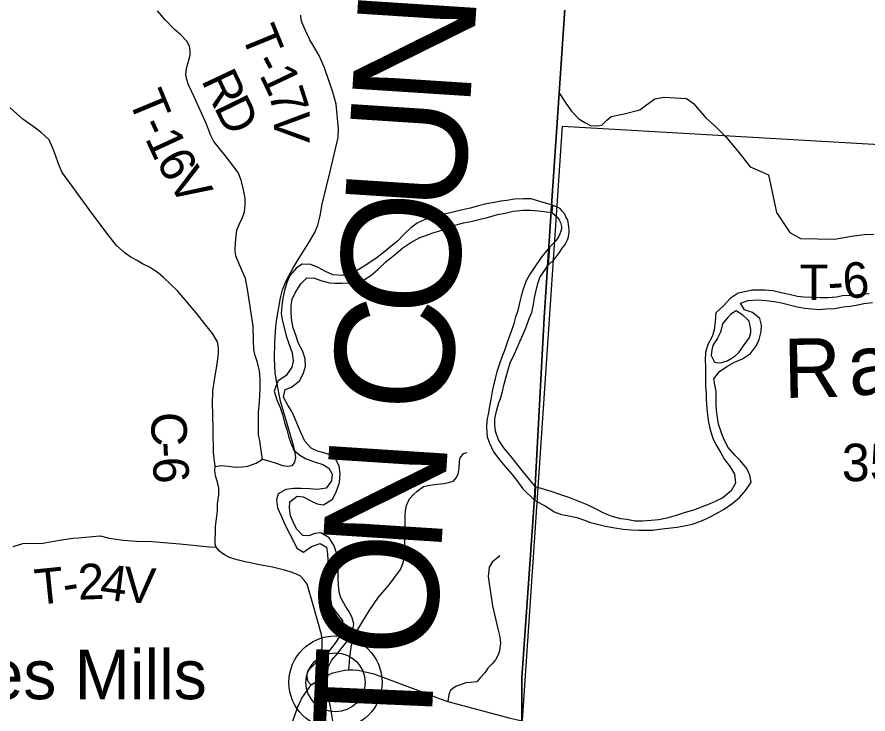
# Model space of a CAD drawing. Extents: x 0 to 34, y 0 to 22.
# Drawn here: x 3.447 to 4.807, y 18.997 to 20.111 of the extents above; entities that cross this region are included whole.
import ezdxf

# ---------------------------------------------------------------- set-up
doc = ezdxf.new("R2010")
doc.units = 0
for name, color, linetype in [('GM_X_Corporation', 7, 'Continuous'), ('GM_X_County_Road', 7, 'Continuous'), ('GM_X_County_Road_Text', 7, 'Continuous'), ('GM_X_County_Text', 7, 'Continuous'), ('GM_X_Major_River', 7, 'Continuous'), ('GM_X_Major_River_Text', 7, 'Continuous'), ('GM_X_Section_Text', 7, 'Continuous'), ('GM_X_Township_Road', 7, 'Continuous'), ('GM_X_Township_Road_Text', 7, 'Continuous'), ('GM_X_Township_Text', 7, 'Continuous'), ('GM_X_Unincorporated', 7, 'Continuous'), ('GM_X_Unincorporated_Location', 7, 'Continuous'), ('GM_X_Unincorporated_Text', 7, 'Continuous')]:
    doc.layers.add(name, color=color, linetype=linetype)

msp = doc.modelspace()

# ---------------------------------------------------------------- linework, layer by layer
at = {"layer": 'GM_X_Corporation'}
msp.add_lwpolyline([(4.1215, 17.0136), (4.1603, 17.6679), (4.1853, 18.0392), (4.1964, 18.2095), (4.2079, 18.3668), (4.2088, 18.3789), (4.2282, 18.6426), (4.2537, 18.9868), (4.2536, 19.0552), (4.2737, 19.3421), (4.2893, 19.6309), (4.3029, 19.8336), (4.3134, 19.9898), (4.3401, 20.3869), (4.364, 20.7926), (4.3772, 20.9), (2.1, 20.9), (2.1, 14.9497)], dxfattribs=at)
msp.add_lwpolyline([(5.342, 19.878), (5.2756, 18.8667), (4.2512, 18.9319), (4.3184, 19.9368)], close=True, dxfattribs=at)
at = {"layer": 'GM_X_County_Road'}
for points in [[(3.9168, 19.0437), (3.9128, 19.0479), (3.911, 19.0525), (3.9102, 19.0601), (3.9116, 19.0653), (3.9154, 19.0699), (3.9194, 19.0745), (3.9274, 19.0829), (3.9316, 19.0895), (3.934, 19.0973), (3.9346, 19.1073), (3.9342, 19.1163), (3.9332, 19.1241), (3.9204, 19.1697), (3.9104, 19.2048), (3.9056, 19.211), (3.899, 19.2182), (3.8908, 19.2218), (3.883, 19.2248), (3.8742, 19.227), (3.8654, 19.2294), (3.855, 19.2318), (3.8433, 19.2342), (3.8311, 19.2362), (3.8197, 19.2388), (3.8113, 19.2406), (3.8007, 19.2432), (3.7925, 19.2452), (3.7853, 19.2482), (3.7791, 19.251), (3.7737, 19.2548), (3.7695, 19.2582), (3.7647, 19.2638), (3.7633, 19.2686), (3.7633, 19.2778), (3.7639, 19.2848), (3.7641, 19.2968), (3.7655, 19.3094), (3.7669, 19.3218), (3.7673, 19.3335), (3.7693, 19.3479), (3.7693, 19.3585), (3.7669, 19.3681), (3.7637, 19.3779), (3.7629, 19.3865), (3.7635, 19.3931), (3.7607, 19.4154), (3.7602, 19.4506), (3.7594, 19.4782), (3.7589, 19.4922), (3.7596, 19.5133), (3.7622, 19.5317), (3.7647, 19.5471), (3.7671, 19.561), (3.7686, 19.5733), (3.7688, 19.583), (3.7671, 19.5922), (3.7592, 19.6054), (3.7485, 19.6189), (3.7332, 19.6388), (3.703, 19.674), (3.6806, 19.6953), (3.6721, 19.7027), (3.6665, 19.7065), (3.6581, 19.7115), (3.6472, 19.7167), (3.6384, 19.722), (3.6285, 19.7274), (3.6193, 19.734), (3.6058, 19.7462), (3.5902, 19.7661), (3.5619, 19.8036), (3.5318, 19.845), (3.5189, 19.8631), (3.5129, 19.8766), (3.5081, 19.8906), (3.5035, 19.9027), (3.4979, 19.9149), (3.4859, 19.9266), (3.4763, 19.934), (3.4561, 19.948), (3.4313, 19.9702)], [(3.9168, 19.0437), (3.9261, 19.0496), (3.9355, 19.0554), (3.9447, 19.06), (3.9516, 19.0629), (3.9608, 19.0652), (3.9701, 19.0674), (3.9771, 19.0681), (3.9835, 19.0677), (3.992, 19.0674), (4.001, 19.065), (4.0168, 19.0614), (4.0442, 19.0511), (4.0739, 19.0399), (4.1079, 19.0272), (4.1213, 19.0223), (4.1351, 19.017), (4.2352, 18.9904), (4.2539, 18.9862)], [(3.5195, 18.4353), (3.5205, 18.4371), (3.5398, 18.4705), (3.5489, 18.484), (3.5628, 18.5), (3.5942, 18.5239), (3.6761, 18.5868), (3.7791, 18.6664), (3.7951, 18.68), (3.809, 18.6975), (3.8193, 18.716), (3.8275, 18.7388), (3.8353, 18.7655), (3.8433, 18.8163), (3.8461, 18.8329), (3.8573, 18.885), (3.8738, 18.9436), (3.8854, 18.9794), (3.8952, 19.0076), (3.9018, 19.0226), (3.9168, 19.0437)]]:
    msp.add_lwpolyline(points, dxfattribs=at)
at = {"layer": 'GM_X_Major_River'}
for p, q in [((4.3024, 19.8106), (4.3016, 19.7988)), ((4.2978, 19.7433), (4.2959, 19.715)), ((4.2757, 19.3602), (4.2745, 19.3384))]:
    msp.add_line(p, q, dxfattribs=at)
for points in [[(4.3024, 19.8106), (4.2825, 19.8168), (4.2684, 19.8206), (4.2563, 19.821), (4.2419, 19.8203), (4.2297, 19.8184), (4.2202, 19.8169), (4.2092, 19.815), (4.1974, 19.8127), (4.1845, 19.8097), (4.1712, 19.8059), (4.1564, 19.8025), (4.1462, 19.8002), (4.1344, 19.7972), (4.1237, 19.7953), (4.1131, 19.793), (4.1002, 19.7885), (4.0861, 19.7817), (4.0763, 19.7745), (4.0668, 19.7654), (4.0546, 19.7529), (4.0447, 19.7453), (4.0318, 19.7347), (4.0223, 19.7271), (4.012, 19.7199), (4.0014, 19.7131), (3.9919, 19.7074), (3.9778, 19.7013), (3.9657, 19.6983), (3.9516, 19.6994), (3.9399, 19.7044), (3.9281, 19.7108), (3.9163, 19.7158), (3.9027, 19.7162), (3.8932, 19.7105), (3.8829, 19.6984), (3.878, 19.687), (3.8741, 19.6745), (3.8715, 19.6619), (3.8699, 19.6498), (3.8688, 19.6377), (3.8703, 19.6278), (3.8767, 19.602), (3.8816, 19.588), (3.8862, 19.5747), (3.8881, 19.5614), (3.8858, 19.5519), (3.8767, 19.5383), (3.8637, 19.5292), (3.8576, 19.5136), (3.8618, 19.4996), (3.8671, 19.487), (3.8709, 19.476), (3.8743, 19.4635), (3.8777, 19.4521), (3.8807, 19.4415), (3.8838, 19.432), (3.8891, 19.4191), (3.8989, 19.4111), (3.9088, 19.4054), (3.9221, 19.4005), (3.9357, 19.3959), (3.9452, 19.3902), (3.9502, 19.3807), (3.9494, 19.3701), (3.9406, 19.3584), (3.927, 19.3561), (3.9141, 19.3572), (3.9011, 19.3576), (3.889, 19.3576), (3.8761, 19.3561), (3.8643, 19.3493), (3.8616, 19.3398), (3.8631, 19.3269), (3.8688, 19.314), (3.876, 19.2981), (3.8825, 19.2848), (3.8889, 19.2723), (3.8938, 19.2624), (3.9045, 19.256), (3.9174, 19.265), (3.9311, 19.27), (3.9413, 19.2639), (3.9432, 19.2533), (3.9436, 19.243), (3.9435, 19.2297), (3.9431, 19.2187), (3.9428, 19.2085), (3.9431, 19.196), (3.9443, 19.1857), (3.9477, 19.1724), (3.9568, 19.1595), (3.967, 19.147), (3.967, 19.1337), (3.9632, 19.1235), (3.9567, 19.1125), (3.9476, 19.1011), (3.9388, 19.0886), (3.9331, 19.0776), (3.9297, 19.0632), (3.9282, 19.0522)], [(4.2959, 19.715), (4.3057, 19.7244), (4.3091, 19.7289), (4.3122, 19.7327), (4.3149, 19.7369), (4.3183, 19.7418), (4.3217, 19.7463), (4.3244, 19.7509), (4.3267, 19.7554), (4.3282, 19.7599), (4.329, 19.7637), (4.3294, 19.7679), (4.3294, 19.7717), (4.329, 19.7759), (4.3283, 19.7797), (4.3275, 19.7839), (4.3264, 19.7877), (4.3242, 19.7918), (4.3223, 19.7964), (4.3181, 19.8013), (4.3151, 19.8055), (4.3024, 19.8106)], [(3.9445, 19.0286), (3.943, 19.0419), (3.9422, 19.0537), (3.9426, 19.0632), (3.9445, 19.0734), (3.9491, 19.0829), (3.9593, 19.0943), (3.9666, 19.1038), (3.9776, 19.1174), (3.9829, 19.1284), (3.9848, 19.1413), (3.9822, 19.1508), (3.978, 19.1603), (3.9716, 19.1698), (3.9644, 19.1831), (3.9617, 19.1925), (3.9606, 19.2035), (3.9598, 19.2134), (3.9599, 19.2248), (3.9595, 19.2388), (3.9587, 19.2498), (3.9538, 19.2662), (3.9455, 19.2791), (3.9322, 19.2867), (3.9227, 19.2859), (3.9132, 19.2821), (3.9037, 19.2825), (3.8935, 19.2935), (3.8882, 19.3045), (3.884, 19.314), (3.8821, 19.3269), (3.8829, 19.3364), (3.8943, 19.3455), (3.9042, 19.3444), (3.9163, 19.3383), (3.9266, 19.3333), (3.9364, 19.3318), (3.9509, 19.3405), (3.957, 19.3519), (3.9619, 19.3671), (3.9634, 19.3815), (3.9616, 19.394), (3.954, 19.4084), (3.9392, 19.4145), (3.9267, 19.4176), (3.9168, 19.4225), (3.9065, 19.4335), (3.9009, 19.446), (3.8956, 19.4586), (3.8906, 19.4703), (3.8861, 19.481), (3.8796, 19.4908), (3.8724, 19.5037), (3.8755, 19.5159), (3.8854, 19.52), (3.8983, 19.5299), (3.904, 19.5409), (3.9078, 19.5526), (3.9071, 19.5648), (3.9033, 19.5769), (3.8968, 19.5898), (3.8923, 19.6031), (3.8878, 19.6145), (3.8859, 19.6255), (3.8847, 19.6388), (3.8851, 19.6498), (3.8867, 19.6604), (3.8912, 19.6703), (3.9004, 19.6851), (3.9099, 19.6945), (3.922, 19.6938), (3.9323, 19.6904), (3.9459, 19.6866), (3.9554, 19.6858), (3.9664, 19.6858), (3.9771, 19.6865), (3.9911, 19.6877), (4.0006, 19.6907), (4.012, 19.6983), (4.0234, 19.7081), (4.0363, 19.7199), (4.0493, 19.7309), (4.0633, 19.7426), (4.0762, 19.751), (4.0903, 19.7589), (4.1002, 19.7623), (4.1116, 19.7665), (4.1226, 19.7695), (4.1385, 19.776), (4.1484, 19.7794), (4.1606, 19.7824), (4.1723, 19.7847), (4.1872, 19.7881), (4.1989, 19.7911), (4.2149, 19.7956), (4.227, 19.7979), (4.2396, 19.8013), (4.2559, 19.8028), (4.2673, 19.8028), (4.2802, 19.8017), (4.3016, 19.7988)], [(4.3016, 19.7988), (4.3101, 19.7915), (4.3135, 19.7873), (4.3154, 19.7828), (4.3169, 19.7767), (4.3173, 19.7729), (4.3161, 19.7691), (4.3146, 19.7649), (4.313, 19.7611), (4.31, 19.757), (4.3069, 19.7528), (4.2978, 19.7433)], [(4.2978, 19.7433), (4.2847, 19.7269), (4.2744, 19.7121), (4.266, 19.6992), (4.2607, 19.6897), (4.2554, 19.6749), (4.2527, 19.6651), (4.2497, 19.6545), (4.247, 19.6423), (4.2432, 19.6302), (4.2401, 19.6192), (4.2367, 19.6086), (4.2329, 19.5987), (4.2291, 19.5881), (4.2257, 19.5786), (4.2215, 19.5676), (4.2177, 19.557), (4.2135, 19.5441), (4.2108, 19.5335), (4.2081, 19.5225), (4.2062, 19.5126), (4.2039, 19.5001), (4.202, 19.4895), (4.2001, 19.4792), (4.1978, 19.4663), (4.197, 19.4546), (4.1982, 19.4405), (4.202, 19.4303), (4.2084, 19.4162), (4.2183, 19.4033), (4.2262, 19.3934), (4.2384, 19.3802), (4.2459, 19.3703), (4.2554, 19.357), (4.2745, 19.3384)], [(4.2757, 19.3602), (4.2565, 19.3837), (4.2357, 19.4098), (4.2247, 19.423), (4.2164, 19.4356), (4.2115, 19.4496), (4.2103, 19.4591), (4.2104, 19.469), (4.213, 19.4815), (4.2161, 19.4929), (4.2203, 19.5035), (4.2229, 19.513), (4.2252, 19.5243), (4.2287, 19.5361), (4.2313, 19.5456), (4.2351, 19.5585), (4.2412, 19.5721), (4.2462, 19.5828), (4.2507, 19.5938), (4.2557, 19.6044), (4.2603, 19.6158), (4.2656, 19.6294), (4.2694, 19.6389), (4.2721, 19.6518), (4.274, 19.6624), (4.2759, 19.6719), (4.2793, 19.6856), (4.2824, 19.695), (4.2959, 19.715)], [(4.8092, 19.6692), (4.7955, 19.6681), (4.7815, 19.6665), (4.7664, 19.6657), (4.7566, 19.6634), (4.7429, 19.6626), (4.7304, 19.6626), (4.7172, 19.6629), (4.7043, 19.6636), (4.6941, 19.6648), (4.6812, 19.6677), (4.668, 19.6707), (4.6551, 19.6737), (4.6422, 19.6748), (4.6225, 19.6748), (4.6123, 19.6729), (4.5995, 19.6698), (4.5866, 19.6614), (4.576, 19.65), (4.5639, 19.6386), (4.5625, 19.6246), (4.561, 19.6109), (4.558, 19.6007), (4.5508, 19.5878), (4.5474, 19.5752), (4.5467, 19.5627), (4.5471, 19.5532), (4.5471, 19.5316), (4.5475, 19.5203), (4.5483, 19.5108), (4.5483, 19.5013), (4.5487, 19.4918), (4.5507, 19.4752), (4.5522, 19.4638), (4.5549, 19.4517), (4.5591, 19.438), (4.5636, 19.4282), (4.572, 19.4146), (4.5777, 19.4043), (4.5868, 19.3922), (4.5936, 19.3805), (4.5952, 19.3665), (4.5884, 19.354), (4.5752, 19.3429), (4.5627, 19.3372), (4.5529, 19.3326), (4.5283, 19.3231), (4.5147, 19.3192), (4.5003, 19.3147), (4.4852, 19.3104), (4.4727, 19.3078)], [(4.5408, 19.306), (4.5518, 19.311), (4.5639, 19.3171), (4.5771, 19.3247), (4.5896, 19.3335), (4.6017, 19.3434), (4.6119, 19.3552), (4.6202, 19.3681), (4.6183, 19.3791), (4.6133, 19.3897), (4.6034, 19.4021), (4.594, 19.4112), (4.5837, 19.4233), (4.5765, 19.4366), (4.5727, 19.4468), (4.5681, 19.4608), (4.5666, 19.4714), (4.565, 19.4832), (4.5643, 19.4926), (4.5642, 19.5127), (4.5623, 19.5233), (4.5604, 19.5332), (4.5694, 19.5446), (4.5815, 19.553), (4.5936, 19.5598), (4.6065, 19.5652), (4.619, 19.5735), (4.6288, 19.5865), (4.6333, 19.596), (4.6363, 19.6089), (4.637, 19.6191), (4.6344, 19.6297), (4.6226, 19.6391), (4.6097, 19.6433), (4.6033, 19.6539), (4.6154, 19.6581), (4.6298, 19.6593), (4.6445, 19.6582), (4.657, 19.6567), (4.6688, 19.6544), (4.6938, 19.6484), (4.7059, 19.6462), (4.718, 19.6451), (4.729, 19.644), (4.7396, 19.6448), (4.7543, 19.6456), (4.7676, 19.6483), (4.7785, 19.6494), (4.7884, 19.6506), (4.8005, 19.6533), (4.8141, 19.6552)], [(4.5961, 19.6417), (4.5878, 19.6364), (4.5829, 19.6311), (4.5791, 19.6269), (4.5746, 19.6208), (4.5727, 19.6136), (4.5712, 19.6079), (4.5667, 19.598), (4.5591, 19.5863), (4.5573, 19.5794), (4.5565, 19.5703), (4.5618, 19.5597)], [(4.5618, 19.5597), (4.5668, 19.5586), (4.5732, 19.5594), (4.5766, 19.5602), (4.5819, 19.5621), (4.5883, 19.5655), (4.5947, 19.5701), (4.6008, 19.575), (4.608, 19.586), (4.614, 19.5936), (4.6174, 19.5989), (4.6196, 19.6073), (4.62, 19.6118), (4.6173, 19.6251), (4.6151, 19.6274), (4.6067, 19.6349), (4.5961, 19.6417)], [(4.3193, 19.3466), (4.2987, 19.3534), (4.2757, 19.3602)], [(4.4727, 19.3078), (4.4602, 19.3066), (4.4466, 19.3054), (4.4344, 19.3057), (4.4216, 19.308), (4.4117, 19.3095), (4.3981, 19.3128), (4.3848, 19.3185), (4.3704, 19.326), (4.3568, 19.3324), (4.3435, 19.3377), (4.3303, 19.3426), (4.3193, 19.3466)], [(4.2745, 19.3384), (4.2921, 19.3296)], [(4.2921, 19.3296), (4.3053, 19.3205), (4.3171, 19.316), (4.3288, 19.3142), (4.3417, 19.3115), (4.3538, 19.3074), (4.3633, 19.3036), (4.3746, 19.301), (4.3875, 19.2977), (4.4023, 19.2947), (4.4159, 19.2928), (4.4288, 19.2917), (4.4405, 19.291), (4.4504, 19.291), (4.4625, 19.2914), (4.4738, 19.2926), (4.4878, 19.2941), (4.5015, 19.2957), (4.5166, 19.2988), (4.5264, 19.3007), (4.5408, 19.306)], [(3.9282, 19.0522), (3.927, 19.0393), (3.9266, 19.0264), (3.9266, 19.0165), (3.9277, 19.0051), (3.9315, 18.9896)], [(3.9516, 18.9865), (3.9494, 18.999), (3.9475, 19.0085), (3.9456, 19.0192), (3.9445, 19.0286)]]:
    msp.add_lwpolyline(points, dxfattribs=at)
at = {"layer": 'GM_X_Township_Road'}
for points in [[(3.7635, 19.3931), (3.7727, 19.3945), (3.7849, 19.3932), (3.7957, 19.3919), (3.8066, 19.3922), (3.8158, 19.3932), (3.829, 19.3981), (3.8388, 19.4049), (3.8372, 19.4149), (3.8346, 19.4343), (3.8328, 19.4432), (3.8324, 19.4703), (3.8324, 19.4791), (3.8341, 19.4963), (3.8351, 19.5175), (3.8354, 19.5325), (3.8344, 19.546), (3.8311, 19.5593), (3.827, 19.572), (3.8252, 19.58), (3.8247, 19.5943), (3.8239, 19.6172), (3.8152, 19.6763), (3.8119, 19.6935), (3.802, 19.7152), (3.7962, 19.7295), (3.7954, 19.7383), (3.7961, 19.7511), (3.7969, 19.7613), (3.7982, 19.7707), (3.8015, 19.7797), (3.8069, 19.7911), (3.8102, 19.8001), (3.8114, 19.8116), (3.8112, 19.822), (3.8084, 19.8351), (3.805, 19.8506), (3.8, 19.8631), (3.7791, 19.8899), (3.7614, 19.9124), (3.7558, 19.9231), (3.7497, 19.9404), (3.7298, 19.9838), (3.7206, 20.0031), (3.7179, 20.0114), (3.7165, 20.0195), (3.7175, 20.0294), (3.7203, 20.0387), (3.7232, 20.0503), (3.7235, 20.0577), (3.7221, 20.0649), (3.7178, 20.073), (3.7087, 20.083), (3.6984, 20.0914), (3.6834, 20.1072), (3.6712, 20.1215)], [(3.8388, 19.4049), (3.8507, 19.4013), (3.8624, 19.3978), (3.8711, 19.3945), (3.8795, 19.3934), (3.887, 19.3947), (3.8906, 19.3998), (3.8921, 19.4073), (3.8913, 19.4154), (3.889, 19.4246), (3.8862, 19.434), (3.8678, 19.4975), (3.8617, 19.5271), (3.8591, 19.5429), (3.8581, 19.5656), (3.8586, 19.5914), (3.8602, 19.6162), (3.8619, 19.6292), (3.8679, 19.6626), (3.8711, 19.6756), (3.8773, 19.6906), (3.8874, 19.7096), (3.8969, 19.7254), (3.902, 19.733), (3.9128, 19.7498), (3.9229, 19.7669), (3.9275, 19.7787), (3.9313, 19.7934), (3.9344, 19.8121), (3.9471, 19.8647), (3.9602, 19.919), (3.9605, 19.9327), (3.9568, 19.972), (3.9512, 19.9914), (3.9388, 20.0286), (3.9352, 20.0378), (3.9295, 20.0498), (3.9229, 20.0618), (3.9145, 20.0749), (3.9078, 20.0897), (3.9033, 20.0996), (3.901, 20.1065), (3.9002, 20.1144)], [(4.3136, 19.9893), (4.3242, 19.9737), (4.3331, 19.9611), (4.3446, 19.9488), (4.3541, 19.9427), (4.3633, 19.9379), (4.375, 19.9376), (4.3817, 19.9387), (4.3896, 19.9468), (4.3963, 19.9527), (4.4175, 19.9569), (4.4422, 19.9629), (4.4529, 19.9711), (4.4663, 19.9806), (4.4814, 19.9831), (4.499, 19.9823), (4.5169, 19.9812), (4.5281, 19.9731), (4.5476, 19.9505), (4.5635, 19.9365), (4.58, 19.92), (4.5987, 19.8969), (4.6185, 19.872), (4.6384, 19.8636), (4.6479, 19.8594), (4.6607, 19.7988), (4.6777, 19.7734)], [(4.6777, 19.7734), (4.6819, 19.767), (4.6992, 19.7575), (4.7533, 19.7565), (4.7807, 19.7611), (4.8017, 19.7637), (4.8162, 19.7645)], [(3.9771, 19.0681), (3.9775, 19.0734), (3.9786, 19.0883), (3.9815, 19.1078), (3.9867, 19.1241), (3.9978, 19.1431), (4.0097, 19.1623), (4.0244, 19.184), (4.0416, 19.2039), (4.0594, 19.2285), (4.0639, 19.2389), (4.0657, 19.2481), (4.0666, 19.272), (4.0662, 19.2842), (4.067, 19.3019), (4.0673, 19.3141), (4.0675, 19.3224), (4.0691, 19.3305), (4.074, 19.341), (4.0804, 19.3483), (4.0863, 19.3535), (4.0965, 19.3608), (4.1066, 19.3633), (4.1179, 19.3648), (4.1293, 19.3659), (4.1363, 19.3671), (4.1445, 19.3695), (4.1487, 19.3747), (4.1517, 19.3809), (4.1535, 19.3903), (4.1541, 19.4015), (4.1548, 19.4069), (4.1603, 19.4136), (4.1662, 19.4155)], [(3.4402, 19.2652), (3.456, 19.2697), (3.4663, 19.2702), (3.4851, 19.27), (3.5142, 19.2751), (3.5359, 19.2782), (3.5446, 19.2791), (3.5671, 19.2812), (3.5793, 19.2819), (3.5938, 19.2786), (3.6163, 19.2751), (3.6375, 19.2736), (3.6622, 19.273), (3.7066, 19.2694), (3.7541, 19.2644), (3.7647, 19.2638)], [(4.2182, 19.2501), (4.2064, 19.24), (4.2014, 19.2322), (4.1999, 19.2173), (4.2009, 19.2094), (4.2066, 19.1703), (4.2153, 19.1333), (4.2186, 19.1206), (4.2194, 19.1102), (4.2185, 19.1036), (4.2177, 19.0976), (4.2151, 19.0906), (4.2117, 19.0839), (4.2061, 19.0773), (4.1994, 19.0705), (4.1943, 19.0629), (4.1872, 19.0552), (4.1818, 19.0489), (4.1718, 19.0478), (4.164, 19.0469), (4.1557, 19.044), (4.149, 19.0415), (4.1441, 19.0386), (4.1397, 19.0348), (4.1372, 19.0308), (4.1362, 19.0246), (4.1351, 19.017)]]:
    msp.add_lwpolyline(points, dxfattribs=at)
at = {"layer": 'GM_X_Township_Text'}
msp.add_lwpolyline([(4.3772, 20.9), (4.364, 20.7926), (4.3401, 20.3869), (4.3134, 19.9898), (4.3029, 19.8336), (4.2893, 19.6309), (4.2737, 19.3421), (4.2536, 19.0552), (4.2537, 18.9868), (4.2282, 18.6426), (4.2088, 18.3789), (4.2079, 18.3668), (4.1964, 18.2095), (4.1853, 18.0392), (4.1603, 17.6679), (4.1215, 17.0136)], dxfattribs=at)
at = {"layer": 'GM_X_Unincorporated'}
for radius in [0.0744, 0.0472]:
    msp.add_circle((3.9557, 19.0478), radius, dxfattribs=at)
at = {"layer": 'GM_X_Unincorporated_Location'}
msp.add_line((3.9557, 19.0478), (3.9557, 19.0478), dxfattribs=at)

# ---------------------------------------------------------------- texts
at = {"layer": 'GM_X_County_Road_Text'}
for s, rotation, p in [('C', 271.0538, (3.6608, 19.4796)), ('-', 272.8317, (3.6617, 19.4311)), ('6', 274.2233, (3.6629, 19.4062))]:
    msp.add_text(s, height=0.0568, rotation=rotation, dxfattribs=at).set_placement(p)
at = {"layer": 'GM_X_County_Text'}
for s, rotation, p in [('N', 86.285, (4.1704, 19.9641)), ('U', 86.2853, (4.1595, 19.797)), ('O', 86.285, (4.1487, 19.6298)), ('C', 86.2853, (4.1387, 19.476)), ('N', 86.2943, (4.1242, 19.2515)), ('O', 86.4637, (4.1138, 19.0844)), ('T', 87.4893, (4.1077, 18.9438))]:
    msp.add_text(s, height=0.1894, rotation=rotation, dxfattribs=at).set_placement(p)
at = {"layer": 'GM_X_Major_River_Text'}
for s, rotation, p in [('R', 1.1029, (4.673, 19.5024)), ('ac', 7.102, (4.7799, 19.5044))]:
    msp.add_text(s, height=0.0947, rotation=rotation, dxfattribs=at).set_placement(p)
at = {"layer": 'GM_X_Section_Text'}
msp.add_text('35', height=0.06, rotation=0, dxfattribs=at).set_placement((4.7652, 19.3694))
at = {"layer": 'GM_X_Township_Road_Text'}
for s, rotation, p in [('T', 292.1372, (3.804, 20.0843)), ('-', 297.9278, (3.8226, 20.0392)), ('R', 295.2838, (3.7405, 20.0105)), ('1', 295.385, (3.8333, 20.0192)), ('T', 292.3776, (3.6238, 19.9805)), ('7', 287.8014, (3.8475, 19.9895)), ('D', 296.0196, (3.7608, 19.9676)), ('V', 270.1239, (3.8575, 19.9607)), ('-', 294.4616, (3.6409, 19.9391)), ('1', 294.6608, (3.6506, 19.9177)), ('6', 299.606, (3.6676, 19.8811)), ('V', 302.2015, (3.6864, 19.8483)), ('T', 359.9957, (4.6976, 19.659)), ('6', 5.1433, (4.769, 19.6608)), ('-', 3.7069, (4.7442, 19.6592)), ('2', 2.0718, (3.5447, 19.1799)), ('T', 5.8087, (3.4777, 19.1716)), ('4', 352.6994, (3.5773, 19.1813)), ('V', 356.2091, (3.6157, 19.1765)), ('-', 9.1583, (3.5235, 19.1764))]:
    msp.add_text(s, height=0.0568, rotation=rotation, dxfattribs=at).set_placement(p)
at = {"layer": 'GM_X_Unincorporated_Text'}
msp.add_text('Vales Mills', height=0.078977, rotation=0, dxfattribs=at).set_placement((3.2453, 19.0209))

doc.saveas('drawing.dxf')
